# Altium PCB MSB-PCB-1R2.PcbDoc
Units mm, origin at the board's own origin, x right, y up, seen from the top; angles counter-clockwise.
Board outline 51 x 51 mm, 2 copper layers (Top Layer, Bottom Layer), stack 1.57 mm thick; 48 components, 55 nets, 221 pads, 21 vias.
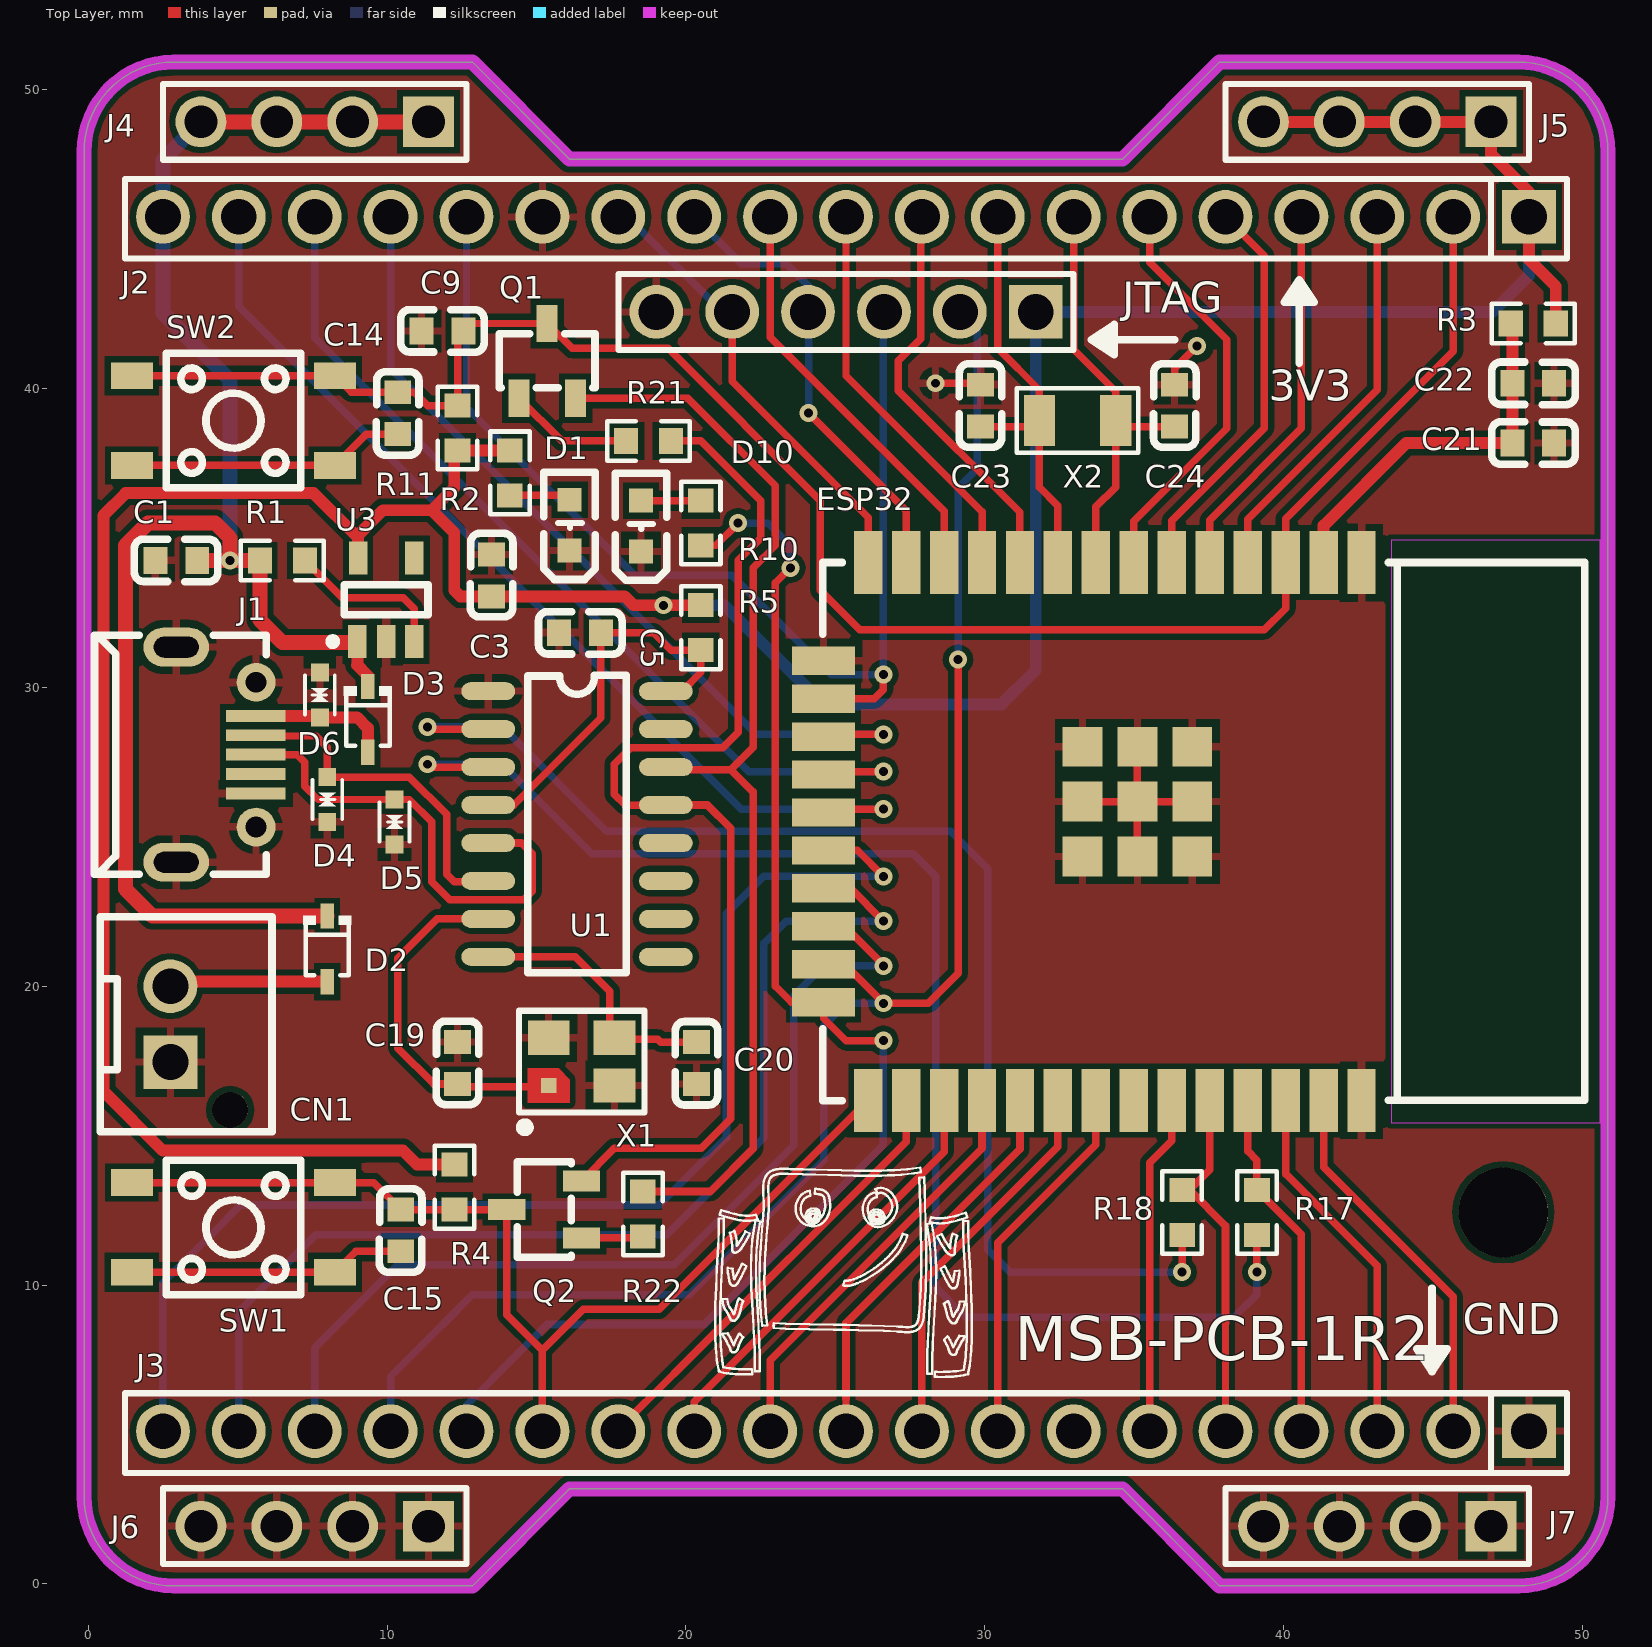
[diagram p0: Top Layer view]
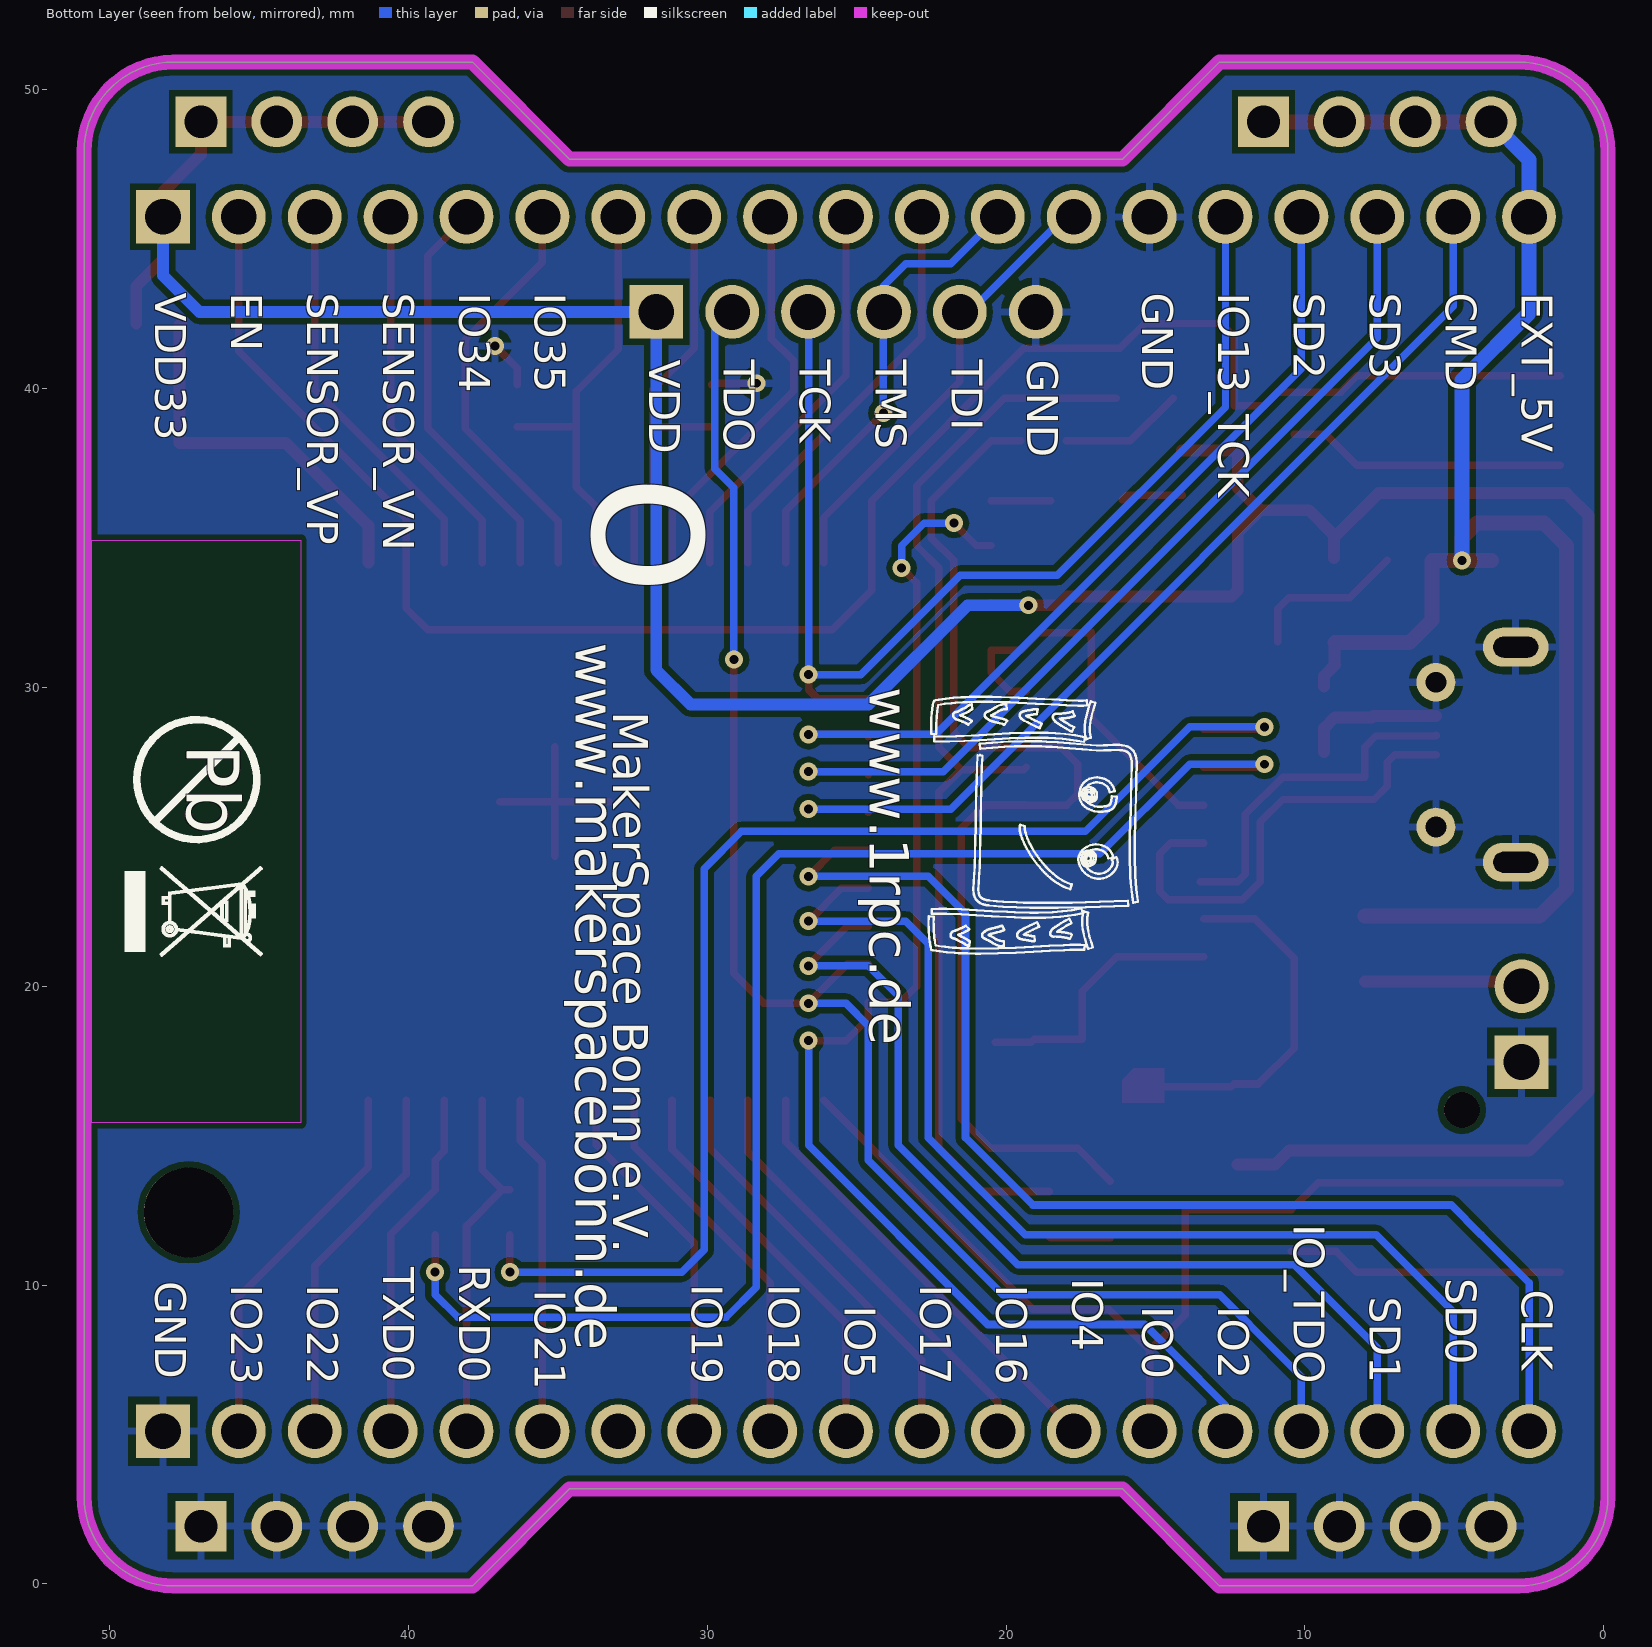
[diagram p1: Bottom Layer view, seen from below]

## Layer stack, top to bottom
Top Solder: solder mask 0.01, Solder Resist, Dk 3.5
Top Layer: signal copper 0.035
Dielectric 1: dielectric 1.5, FR-4, Dk 4.8
Bottom Layer: signal copper 0.035
Bottom Solder: solder mask 0.01, Solder Resist, Dk 3.5

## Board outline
-0.14,2.93 ccw(c2.86,2.93) 2.86,-0.07 12.86,-0.07 16.11,3.18 34.61,3.18 37.86,-0.07 47.86,-0.07 ccw(c47.86,2.93) 50.86,2.93 50.86,47.93 ccw(c47.86,47.93) 47.86,50.93 37.86,50.93 34.61,47.68 16.11,47.68 12.86,50.93 2.86,50.93 ccw(c2.86,47.93) -0.14,47.93

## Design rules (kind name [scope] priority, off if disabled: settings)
Clearance [All] p1: gap=0.2 ignorepadtopadclearanceinfootprint=FALSE
ComponentClearance [All] p1: gap=0.2 collisioncheckmode=3 verticalgap=0.2 showdistances=FALSE
HoleSize [All] p1: absolutevalues=TRUE maxlimit=3.5 minlimit=0.025 maxpercent=80.000 minpercent=20.000
MinimumSolderMaskSliver [All] p1: minsoldermaskwidth=0.05
PolygonConnect [All] p1: connectstyle=Relief reliefconductorwidth=0.254 reliefentries=4 polygonreliefangle="90 Angle" airgapwidth=0.254
RoomDefinition MSB-PCB-1R2 [InComponentClass('MSB-PCB-1R2')] p1: confinementstyle=ConfineIn formatcopy=TRUE lockcomponents=FALSE outline -0.14,-0.07 50.86,-0.07 50.86,50.93 -0.14,50.93
RoutingVias [All] p1: holewidth=0.3 width=0.6 viastyle="Through Hole" minholewidth=0.3 minwidth=0.6 maxholewidth=0.7 maxwidth=1
SilkToSilkClearance [All] p1 off: silktosilkclearance=0.1
SilkToSolderMaskClearance [IsPad] p1: minsilkscreentomaskgap=0.1 clearancetoexposedcopper=TRUE
SolderMaskExpansion [All] p1: expansion=0.102
Width [All] p1: maxlimit=0.6 minlimit=0.2 preferedwidth=0.25
25 further rules are at their usual default settings.

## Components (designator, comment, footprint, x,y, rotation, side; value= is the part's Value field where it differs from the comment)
C1 "22uF" C0603 2.95,34.25 r0 top
C3 "22uF" C0603 13.5,33.75 r270 top
C5 "100nF" C0603 16.46,31.83 r180 top
C9 "100nF" C0603 11.86,41.93 r0 top
C14 "100nF" C0603 10.36,39.18 r90 top
C15 "100nF" C0603 10.46,11.83 r90 top
C19 "20pF" C0603 12.36,17.43 r270 top
C20 "20pF" C0603 20.36,17.43 r90 top
C21 "22uF" C0603 48.36,38.18 r180 top
C22 "100nF" C0603 48.36,40.18 r180 top
C23 "12pF" C0603 29.86,39.43 r270 top
C24 "12pF" C0603 36.36,39.43 r270 top
CN1 "B2B-XH-AM (LF)(SN)" CONN-TH_B2B-XH-AM-LF-SN 2.75,18.73 r270 top
D1 "19-217/GHC-YR1S2/3T" LED0603-R-RD 16.11,35.43 r90 top
D2 "BAT760-7" SOD-323_L1.8-W1.3-LS2.5-RD 8,21.25 r270 top
D3 "BAT760-7" SOD-323_L1.8-W1.3-LS2.5-RD 9.36,28.93 r270 top
D4 "LESD5D5.0CT1G" SOD-523_L1.2-W0.8-LS1.6-BI 8,26.25 r90 top
D5 "LESD5D5.0CT1G" SOD-523_L1.2-W0.8-LS1.6-BI 10.25,25.5 r90 top
D6 "LESD5D5.0CT1G" SOD-523_L1.2-W0.8-LS1.6-BI 7.75,29.75 r270 top
D10 "19-217/BHC-ZL1M2RY/3T" LED0603-R-RD 18.5,35.399 r90 top
ESP32 "ESP32-WROOM-32E(4MB)" WIFI-SMD_ESP32-WROOM-32E 33.61,25.18 r180 top
J1 "MICROXNJ" MICRO-USB-SMD_MICROXNJ 4.283,27.75 r270 top
J2 "12251120CNG0S115005" HDR-TH_19P-P2.54-V 24.09,45.75 r180 top
J3 "12251120CNG0S115005" HDR-TH_19P-P2.54-V 24.09,5.11 r180 top
J4 "MTP125-1104S1" HDR-TH_4P-P2.54-V 7.58,48.93 r180 top
J5 "MTP125-1104S1" HDR-TH_4P-P2.54-V 43.14,48.93 r180 top
J6 "MTP125-1104S1" HDR-TH_4P-P2.54-V 7.58,1.93 r180 top
J7 "MTP125-1104S1" HDR-TH_4P-P2.54-V 43.14,1.93 r180 top
JTAG "MTP125-1106S1" HDR-TH_6P-P2.54-V 25.36,42.57 r180 top
Q1 "S8050_C2146" SOT-23-3_L3.0-W1.7-P0.95-LS2.9-BR 15.36,40.93 r270 top
Q2 "S8050_C2146" SOT-23-3_L3.0-W1.7-P0.95-LS2.9-BR 15.26,12.53 r0 top
R1 "1.8K" R0603 6.497,34.25 r0 top
R2 "560" R0603 14.11,37.18 r90 top
R3 "0" R0603 48.36,42.18 r180 top
R4 "10K" R0603 12.26,13.277 r90 top
R5 "0" R0603 20.5,32 r90 top
R10 "560" R0603 20.5,35.503 r270 top
R11 "10K" R0603 12.36,38.68 r270 top
R17 "270" R0603 39.11,12.43 r270 top
R18 "270" R0603 36.61,12.43 r270 top
R21 "10K" R0603 18.75,38.25 r180 top
R22 "10K" R0603 18.56,12.377 r270 top
SW1 "GT-TC074A-H038-L1" SW-SMD_4P-L4.5-W4.5-P3.00-LS7.0 4.86,11.93 r180 top
SW2 "GT-TC074A-H038-L1" SW-SMD_4P-L4.5-W4.5-P3.00-LS7.0 4.86,38.93 r180 top
U1 "CH340G" SOIC-16_L9.9-W3.9-P1.27-LS6.0-TL 16.36,25.43 r270 top
U3 "AP2112K-3.3TRG1" SOT-25-5_L3.0-W1.8-P0.95-LS3.0-BR 9.96,32.93 r270 top
X1 "12MHz" OSC-SMD_4P-L3.2-W2.5-BL 16.51,17.48 r0 top
X2 "32.768KHz" OSC-SMD_L3.2-W1.5 33.11,38.93 r0 top

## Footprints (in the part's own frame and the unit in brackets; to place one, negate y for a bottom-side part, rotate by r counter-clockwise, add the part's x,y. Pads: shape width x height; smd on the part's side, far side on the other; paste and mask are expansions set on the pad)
C0603 [mm]
  rect 0.8x0.9 smd: 1(-0.7,0) 2(0.7,0)
  silkscreen extent -1.41,-0.71 1.39,0.72
CONN-TH_B2B-XH-AM-LF-SN [mm]
  rect 1.8x1.8 hole 1.2: 1(1.27,0)
  round 1.8 hole 1.2: 2(-1.27,0)
  round 1.2 hole 1.2 unplated: ""(2.87,2)
  silkscreen extent -3.6,-2.35 3.6,3.4
HDR-TH_4P-P2.54-V [mm]
  rect 1.7x1.7 hole 1.1: 1(-3.81,0)
  round 1.7 hole 1.1: 2(-1.27,0) 3(1.27,0) 4(3.81,0)
  silkscreen extent -5.08,-1.27 5.08,1.27
HDR-TH_6P-P2.54-V [mm]
  rect 1.8x1.8 hole 1.2: 1(-6.35,0)
  round 1.8 hole 1.2: 2(-3.81,0) 3(-1.27,0) 4(1.27,0) 5(3.81,0) 6(6.35,0)
  silkscreen extent -7.62,-1.27 7.62,1.27
HDR-TH_19P-P2.54-V [mm]
  rect 1.8x1.8 hole 1.2: 1(-24.13,0)
  round 1.8 hole 1.2: 2(-21.59,0) 3(-19.05,0) 4(-16.51,0) 5(-13.97,0) 6(-11.43,0) 7(-8.89,0) 8(-6.35,0) 9(-3.81,0) 10(-1.27,0) 11(1.27,0) 12(3.81,0) 13(6.35,0) 14(8.89,0) 15(11.43,0) 16(13.97,0) 17(16.51,0) 18(19.05,0) 19(21.59,0)
  silkscreen extent -25.4,-1.27 22.86,1.4
LED0603-R-RD [mm]
  rect 0.8x0.8 smd: 1(0.851,0) 2(-0.851,0)
  silkscreen extent -1.82,-0.86 1.77,0.86
MICRO-USB-SMD_MICROXNJ [mm]
  rect 0.4x2 smd mask+0: 1(-1.3,1.327) 2(-0.65,1.327) 3(0,1.327) 4(0.65,1.327) 5(1.3,1.327)
  round 1.3 hole 0.7: 6(2.425,1.335) 9(-2.425,1.335)
  oval 1.3x2.2 hole 0.7 slot 1.5 at 90 deg: 7(3.6,-1.335) 8(-3.6,-1.335)
  silkscreen extent -4,-4.07 4,1.68
OSC-SMD_4P-L3.2-W2.5-BL [mm]
  rect 0.508x0.508 smd: 1(-1.1,-0.8)
  rect 1.4x1.15 smd: 2(1.1,-0.8) 3(1.1,0.8) 4(-1.1,0.8)
  Top Layer region: -1.8,-0.225 -0.762,-0.225 -0.4,-0.604 -0.4,-1.375 -1.8,-1.375
  silkscreen extent -2.1,-2.35 2.1,1.7
OSC-SMD_L3.2-W1.5 [mm]
  rect 1.05x1.7 smd: 1(-1.275,0) 2(1.275,0)
  silkscreen extent -2.03,-1.08 2.03,1.08
R0603 [mm]
  rect 0.806x0.864 smd: 1(-0.753,0) 2(0.753,0)
  silkscreen extent -1.39,-0.66 1.39,0.66
SOD-323_L1.8-W1.3-LS2.5-RD [mm]
  rect 0.845x0.455 smd: 1(-1.098,0) 2(1.098,0)
  silkscreen extent -1.1,-0.8 0.88,0.8
SOD-523_L1.2-W0.8-LS1.6-BI [mm]
  rect 0.6x0.6 smd: 1(-0.75,0) 2(0.75,0)
  silkscreen extent -0.65,-0.5 0.65,0.5
SOIC-16_L9.9-W3.9-P1.27-LS6.0-TL [mm]
  oval 0.6x1.8 smd: 1(-4.445,-2.972) 2(-3.175,-2.972) 3(-1.905,-2.972) 4(-0.635,-2.972) 5(0.635,-2.972) 6(1.905,-2.972) 7(3.175,-2.972) 8(4.445,-2.972) 9(4.445,2.972) 10(3.175,2.972) 11(1.905,2.972) 12(0.635,2.972) 13(-0.635,2.972) 14(-1.905,2.972) 15(-3.175,2.972) 16(-4.445,2.972)
  silkscreen extent -4.98,-1.65 4.98,1.65
SOT-23-3_L3.0-W1.7-P0.95-LS2.9-BR [mm]
  rect 1.25x0.7 smd: 1(1.25,-0.95) 2(1.25,0.95) 3(-1.25,0)
  silkscreen extent -0.9,-1.6 0.9,1.6
SOT-25-5_L3.0-W1.8-P0.95-LS3.0-BR [mil]
  rect 43.5x24.5 smd: 1(55,-37.5) 2(55,0.5) 3(55,37.5) 4(-55,37.5) 5(-55,-36.5)
  silkscreen extent -20,-75 60,56
SW-SMD_4P-L4.5-W4.5-P3.00-LS7.0 [mm]
  rect 1.4x0.9 smd: 1(-3.4,1.5) 2(3.4,1.5) 3(-3.4,-1.5) 4(3.4,-1.5)
  silkscreen extent -2.25,-2.25 2.25,2.25
WIFI-SMD_ESP32-WROOM-32E [mm]
  rect 0.95x2.1 smd: 1(-9.002,-9) 2(-7.732,-9) 3(-6.462,-9) 4(-5.192,-9) 5(-3.922,-9) 6(-2.652,-9) 7(-1.382,-9) 8(-0.112,-9) 9(1.158,-9) 10(2.428,-9) 11(3.698,-9) 12(4.968,-9) 13(6.238,-9) 14(7.508,-9) 25(7.507,9) 26(6.237,9) 27(4.967,9) 28(3.697,9) 29(2.427,9) 30(1.157,9) 31(-0.113,9) 32(-1.383,9) 33(-2.653,9) 34(-3.923,9) 35(-5.193,9) 36(-6.463,9) 37(-7.733,9) 38(-9.003,9)
  rect 2.1x0.95 smd: 15(9.002,-5.715) 16(9.002,-4.445) 17(9.002,-3.175) 18(9.002,-1.905) 19(9.002,-0.635) 20(9.002,0.635) 21(9.002,1.905) 22(9.002,3.175) 23(9.002,4.445) 24(9.002,5.715)
  rect 1.33x1.33 smd: 39(-3.337,-2.835) 39(-3.337,-1) 39(-3.337,0.835) 39(-1.502,0.835) 39(-1.502,-1) 39(-1.502,-2.835) 39(0.333,0.835) 39(0.333,-1) 39(0.333,-2.835)
  silkscreen extent -16.48,-9 9.02,9.02

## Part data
C1 C3 C21: BOM_JLCPCB Part Class="Extended Part", BOM_Manufacturer="Murata Electronics", BOM_Manufacturer Part=GRM188R61A226ME15L
C5 C9 C14 C15 C22: BOM_JLCPCB SMD=Yes, BOM_Manufacturer=YAGEO, BOM_Manufacturer Part=CC0603KRX7R9BB104
C19 C20: BOM_Manufacturer=CCTC, BOM_Manufacturer Part=TCC0603COG200J500CT
C23 C24: BOM_Manufacturer=CCTC, BOM_Manufacturer Part=TCC0603COG120J500CT
CN1: BOM_JLCPCB Part Class="Extended Part", BOM_Manufacturer="JST Sales America", BOM_Manufacturer Part=-
D1 D10: BOM_JLCPCB Part Class="Basic Part", BOM_Manufacturer=EVERLIGHT
D2 D3: BOM_JLCPCB Part Class="Extended Part", BOM_Manufacturer=DIODES
D4 D5 D6: BOM_JLCPCB Part Class="Extended Part", BOM_Manufacturer="Leshan Radio"
ESP32: BOM_LCSC Assembly=Yes, BOM_Manufacturer="Espressif Systems"
J1: BOM_Manufacturer="SHOU HAN", BOM_Manufacturer Part=MicroXNJ
J2 J3: BOM_JLCPCB Part Class="Extended Part", BOM_Manufacturer=JILN
J4 J5 J6 J7 JTAG: BOM_JLCPCB Part Class="Extended Part", BOM_Manufacturer=MINTRON
Q1 Q2: BOM_JLCPCB SMD=Yes, BOM_Manufacturer=CJ, BOM_Manufacturer Part=S8050
R1: BOM_JLCPCB Part Class="Extended Part", BOM_Manufacturer=UniOhm, BOM_Manufacturer Part=0603WAJ0182T5E
R2 R10: BOM_JLCPCB Part Class="Basic Part", BOM_Manufacturer=UniOhm, BOM_Manufacturer Part=0603WAF5600T5E
R3 R5: BOM_JLCPCB SMD=Yes, BOM_Manufacturer=UniOhm, BOM_Manufacturer Part=0603WAF0000T5E
R4 R11 R21 R22: BOM_JLCPCB Part Class="Extended Part", BOM_Manufacturer=UniOhm, BOM_Manufacturer Part=0603WAJ0103T5E
R17 R18: BOM_JLCPCB Part Class="Extended Part", BOM_Manufacturer=UniOhm, BOM_Manufacturer Part=0603WAJ0271T5E
SW1 SW2: BOM_JLCPCB Part Class="Extended Part", BOM_Manufacturer=G-Switch
U1: BOM_JLCPCB SMD=Yes, BOM_Manufacturer=WCH
U3: BOM_JLCPCB SMD=Yes, BOM_Manufacturer=DIODES
X1: BOM_JLCPCB SMD=Yes, BOM_Manufacturer=YXC, BOM_Manufacturer Part=X322512MSB4SI
X2: BOM_JLCPCB Part Class="Extended Part", BOM_Manufacturer=TKD, BOM_Manufacturer Part=SF32K32768D31T-12.5

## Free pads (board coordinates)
  round 3 hole 3 unplated mask+1: 0(47.36,12.43)

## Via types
v1: diameter 0.6, hole 0.3, Top Layer to Bottom Layer, 21 vias

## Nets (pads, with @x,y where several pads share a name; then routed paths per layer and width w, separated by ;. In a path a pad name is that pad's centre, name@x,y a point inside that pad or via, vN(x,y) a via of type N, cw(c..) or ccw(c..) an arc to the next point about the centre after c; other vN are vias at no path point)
CLK: ESP32.20 J3.19 | length 41.5
  Top Layer w0.25: ESP32.20 25.745,24.545 v1(26.61,23.68)
  Bottom Layer w0.25: J3.19 2.5,10.07 4.11,11.68
  Bottom Layer w0.254: 4.11,11.68 5.11,12.68 19.11,12.68 21.36,14.93 21.36,22.43 22.61,23.68 v1(26.61,23.68)
CMD: ESP32.19 J2.18 | length 33.6
  Top Layer w0.25: ESP32.19 24.723,25.93 v1(26.61,25.93)
  Bottom Layer w0.25: J2.18 5.04,42.75 21.86,25.93 v1(26.61,25.93)
DTR: Q2.2 R21.1 U1.13 | length 37.4
  Top Layer w0.25: U1.13 17.975,26.065 17.61,26.43 17.61,27.43 18.16,27.98 21.23,27.98 21.75,28.5 21.75,34.25 22.5,35 22.5,36.25 20.5,38.25 R21.1
  Top Layer w0.254: Q2.2 17.61,14.58 20.51,14.58 21.5,15.57 21.5,25.29 20.725,26.065 U1.13
EN: C9.2 C14.2 ESP32.3 J2.2 Q1.3 R11.1 SW2.3 SW2.4 | length 63.2
  Top Layer w0.25: SW2.4 SW2.3 8.81,39.88 10.91,39.88 11.357,39.433 R11.1 12.36,41.73 C9.2 12.81,42.18 Q1.3 16.195,41.345 19.405,41.345 24.5,36.25 24.5,33.25 25.82,31.93 39.36,31.93 40.072,32.642 ESP32.3 40.072,35.642 45.68,41.25 J2.2
EXT_5V: C1.2 D2.1 D3.1 J2.19 J4.1 J4.2 J4.3 J4.4 R1.1 U3.1 | length 56.3
  Top Layer w0.4: 9,30.75 9.36,30.39 D3.1 ; 9.007,30.783 U3.1
  Top Layer w0.5: C1.2@3.75,34.25 v1(4.75,34.25) ; J4.4 J4.3 J4.2 J4.1 ; D2.1 2.152,22.348 1.25,23.25 1.25,34.75 2,35.5 4.25,35.5 4.75,35 v1(4.75,34.25) ; U3.1@9,31.5 6.5,31.5 5.744,32.256 R1.1 v1(4.75,34.25)
  Bottom Layer w0.5: J4.4 2.5,47.66 J2.19 2.5,42.53 4.75,40.28 v1(4.75,34.25)
GND: C1.1 C3.1 C5.2 C9.1 C19.1 C20.1 C21.1 C22.1 C23.1 C24.1 CN1.1 D1.2 D4.1 D5.1 D6.1 D10.2 ESP32.1 ESP32.15 ESP32.38 ESP32.39 J1.5 J1.6 J1.7 J1.8 J1.9 J2.14 J3.1 J6.1 J6.2 J6.3 J6.4 J7.1 J7.2 J7.3 J7.4 JTAG.6 U1.1 U3.2 X1.2 X1.4 | length 11.1
  Top Layer w0.25: J2.14 J2.14@15.2,46.39 ; v1(28.36,40.18) 29.81,40.18 C23.1 ; ESP32.39@33.277,26.18 ESP32.39@35.112,26.18 ; ESP32.39@35.112,24.345 ESP32.39@35.112,26.18 ; ESP32.39@35.112,28.015 ESP32.39@35.112,26.18 ; C24.1 36.36,40.68 v1(37.11,41.43) ; ESP32.39@36.947,26.18 ESP32.39@35.112,26.18
IO0: C15.2 ESP32.25 J3.14 Q2.3 R4.1 SW1.3 SW1.4 | length 35.2
  Top Layer w0.25: SW1.4 9.56,13.43 10.466,12.524 14.004,12.524 Q2.3 14.01,9.007 15.2,7.817 16.57,9.187 19.11,9.187 ESP32.25 ; J3.14 15.2,7.77
IO2: ESP32.24 J3.15 R10.2 | length 45.2
  Top Layer w0.25: R10.2 21,34.75 v1(21.75,35.5) ; v1(23.5,34) 23,33.5 23,20 23.535,19.465 ESP32.24 24.608,18.932 25.36,18.18 v1(26.61,18.18)
  Bottom Layer w0.25: J3.15 12.66,5.98 14.36,7.68 ; v1(21.75,35.5) 22.75,35.5 23.5,34.75 v1(23.5,34)
  Bottom Layer w0.254: 14.36,7.68 15.36,8.68 20.61,8.68 26.61,14.68 v1(26.61,18.18)
IO4: ESP32.26 J3.13 | length 15.1
  Top Layer w0.25: J3.13 17.74,5.17 19.61,7.04
  Top Layer w0.254: 19.61,7.04 27.373,14.803 ESP32.26
IO5: ESP32.29 J3.10 | length 13.5
  Top Layer w0.25: J3.10 25.36,6.18
  Top Layer w0.254: 25.36,6.18 25.36,8.73 31.183,14.553 ESP32.29
IO12_TDI: ESP32.14 J2.13 JTAG.5 | length 15.4
  Top Layer w0.25: JTAG.5 21.55,40.24 26.102,35.688 ESP32.14
  Bottom Layer w0.25: J2.13 18.04,45.75 21.22,42.57 JTAG.5
IO13_TCK: ESP32.16 J2.15 JTAG.3 | length 38.8
  Top Layer w0.25: ESP32.16 26.305,29.625 26.61,29.93 v1(26.61,30.43)
  Bottom Layer w0.25: J2.15 12.66,39.38 18.29,33.75 21.54,33.75 24.86,30.43 v1(26.61,30.43) 26.61,42.55 JTAG.3
IO14_TMS: ESP32.13 J2.12 JTAG.4 | length 15.5
  Top Layer w0.25: J2.12 J2.12@20.325,45.705 ; v1(24.11,39.18) 27.372,35.918 ESP32.13
  Bottom Layer w0.25: J2.12 21.85,44.18 23.36,44.18 24.09,43.45 JTAG.4 24.11,42.55 v1(24.11,39.18)
IO15_TDO: ESP32.23 J3.16 JTAG.2 | length 54.2
  Top Layer w0.25: ESP32.23 25.322,20.735 26.61,19.447 v1(26.61,19.43) 28.11,19.43 29.11,20.43 v1(29.11,30.93)
  Bottom Layer w0.25: J3.16 10.12,6.94 11.86,8.68 ; v1(29.11,30.93) 29.11,36.68 29.75,37.32 29.75,41.99 JTAG.2
  Bottom Layer w0.254: 11.86,8.68 12.86,9.68 20.11,9.68 24.61,14.18 24.61,18.68 25.36,19.43 v1(26.61,19.43)
IO16: ESP32.27 J3.12 | length 14.5
  Top Layer w0.25: J3.12 20.28,6.1 21.55,7.37
  Top Layer w0.254: 21.55,7.37 28.643,14.463 ESP32.27
IO17: ESP32.28 J3.11 | length 14
  Top Layer w0.25: J3.11 22.82,6.14
  Top Layer w0.254: 22.82,6.14 22.82,7.49 29.913,14.583 ESP32.28
IO18: ESP32.30 J3.9 | length 13
  Top Layer w0.25: J3.9 27.9,10.07
  Top Layer w0.254: 27.9,10.07 32.453,14.623 ESP32.30
IO19: ESP32.31 J3.8 | length 12.4
  Top Layer w0.25: J3.8 30.44,6.26
  Top Layer w0.254: 30.44,6.26 30.44,11.41 33.723,14.693 ESP32.31
IO21: ESP32.33 J3.6 | length 11.4
  Top Layer w0.25: J3.6 35.52,8.77
  Top Layer w0.254: 35.52,8.77 35.52,14.09 36.263,14.833 ESP32.33
IO22: ESP32.36 J3.3 | length 12.3
  Top Layer w0.25: 42.61,11.18 43.14,10.65 J3.3
  Top Layer w0.254: ESP32.36 40.073,13.717 42.61,11.18
IO23: ESP32.37 J3.2 | length 12.9
  Top Layer w0.25: 43.86,11.43 45.68,9.61 J3.2
  Top Layer w0.254: ESP32.37 41.343,13.947 43.86,11.43
IO25: ESP32.10 J2.9 | length 13.6
  Top Layer w0.25: J2.9 27.855,45.705 27.855,41.675 27.11,40.93 27.11,39.93 31.182,35.858 ESP32.10
IO26: ESP32.11 J2.10 | length 13.5
  Top Layer w0.25: J2.10 25.36,40.43 29.912,35.878 ESP32.11
IO27: ESP32.12 J2.11 | length 14
  Top Layer w0.25: J2.11 22.82,41.72 28.642,35.898 ESP32.12
IO32: C24.2 ESP32.8 J2.7 X2.2 | length 14.4
  Top Layer w0.25: J2.7 32.98,41.31 34.385,39.905 X2.2 X2.2@34.385,38.68 ; ESP32.8 33.722,36.042 34.385,36.705 X2.2@34.385,38.68 ; C24.2 34.435,38.73 X2.2@34.385,38.68
IO33: C23.2 ESP32.9 J2.8 X2.1 | length 14.5
  Top Layer w0.25: C23.2 31.635,38.73 X2.1 ; J2.8 30.44,41.35 31.835,39.955 X2.1 ; ESP32.9 32.452,36.088 31.835,36.705 X2.1
IO34: ESP32.6 J2.5 | length 13.4
  Top Layer w0.25: ESP32.6 36.262,35.582 39.36,38.68 39.36,44.45 J2.5
IO35: ESP32.7 J2.6 | length 13.9
  Top Layer w0.25: ESP32.7 34.992,35.562 38.11,38.68 38.11,41.64 35.52,44.23 J2.6
NetC14_1: C14.1 SW2.1 SW2.2 | length 9.3
  Top Layer w0.25: SW2.2 SW2.1 9.31,38.48 C14.1
NetC15_1: C15.1 SW1.1 SW1.2 | length 9.3
  Top Layer w0.25: SW1.2 SW1.1 8.96,11.13 C15.1
NetC19_2: C19.2 U1.7 X1.1 | length 12
  Top Layer w0.25: C19.2 12.46,16.63 X1.1@15.26,16.63
  Top Layer w0.254: C19.2 11.56,16.73 10.36,17.93 10.36,20.93 11.685,22.255 U1.7
NetC20_2: C20.2 U1.8 X1.3 | length 9.1
  Top Layer w0.254: U1.8 16.305,20.985 17.46,19.83 17.46,18.23 19.06,18.23 19.16,18.13 C20.2
NetCN1_2: CN1.2 D2.2 | length 5.3
  Top Layer w0.4: CN1.2 2.902,20.152 D2.2
NetD1_1: D1.1 R2.1 | length 2.1
  Top Layer w0.25: R2.1 15.964,36.427 D1.1
NetD10_1: D10.1 R10.1 | length 2
  Top Layer w0.25: D10.1 R10.1@20.494,36.25
NetQ1_1: Q1.1 R21.2 | length 4.2
  Top Layer w0.25: Q1.1 15.84,38.25 R21.2
NetQ2_1: Q2.1 R22.2 | length 2.1
  Top Layer w0.25: Q2.1 18.516,11.58 R22.2
NetR1_2: R1.2 U3.3 | length 5.4
  Top Layer w0.25: R1.2 8.5,33 10.54,33 10.912,32.628 U3.3
RTS: Q1.2 R22.1 U1.14 | length 37.5
  Top Layer w0.25: Q1.2 20.07,39.68 23,36.75 23,34.75 22.25,34 22.25,28 21.5,27.25
  Top Layer w0.254: R22.1 20.81,13.13 22.25,14.57 22.25,26.5 21.5,27.25 19.417,27.25 U1.14
RXD: R17.2 U1.3 | length 47.8
  Top Layer w0.25: v1(11.36,27.43) 11.455,27.335 U1.3 ; v1(39.11,10.43) R17.2
  Bottom Layer w0.25: v1(11.36,27.43) 13.86,27.43 16.86,24.43 27.61,24.43 28.36,23.68 28.36,9.93 29.36,8.93 38.36,8.93 39.11,9.68 v1(39.11,10.43)
RXD0: ESP32.34 J3.5 R18.1 | length 12.1
  Top Layer w0.25: J3.5 38.06,8.73
  Top Layer w0.254: R18.1 R18.1@36.857,13.183 ; ESP32.34 37.533,13.853 36.863,13.183 R18.1@36.857,13.183 ; 38.06,8.73 38.06,11.98 R18.1@36.857,13.183
SD0: ESP32.21 J3.18 | length 37.2
  Top Layer w0.25: ESP32.21 25.515,23.275 v1(26.61,22.18)
  Bottom Layer w0.25: J3.18 5.04,9.11 6.36,10.43
  Bottom Layer w0.254: 6.36,10.43 7.61,11.68 19.36,11.68 22.61,14.93 22.61,21.43 23.36,22.18 v1(26.61,22.18)
SD1: ESP32.22 J3.17 | length 32.6
  Top Layer w0.25: ESP32.22 25.322,22.005 26.61,20.717 v1(26.61,20.68)
  Bottom Layer w0.25: J3.17 7.58,7.9 9.605,9.925
  Bottom Layer w0.254: 9.605,9.925 10.36,10.68 19.61,10.68 23.61,14.68 23.61,19.68 24.61,20.68 v1(26.61,20.68)
SD2: ESP32.17 J2.16 | length 28.7
  Top Layer w0.25: ESP32.17 24.683,28.43 v1(26.61,28.43)
  Bottom Layer w0.25: J2.16 10.12,40.67 22.36,28.43 v1(26.61,28.43)
SD3: ESP32.18 J2.17 | length 31.1
  Top Layer w0.25: ESP32.18 24.703,27.18 v1(26.61,27.18)
  Bottom Layer w0.25: J2.17 7.58,41.71 22.11,27.18 v1(26.61,27.18)
SENSOR_VN: ESP32.5 J2.4 | length 12.8
  Top Layer w0.25: ESP32.5 37.532,35.602 40.6,38.67 J2.4
SENSOR_VP: ESP32.4 J2.3 | length 13.4
  Top Layer w0.25: ESP32.4 38.802,35.622 43.14,39.96 J2.3
TXD: R18.2 U1.2 | length 43.6
  Top Layer w0.25: v1(11.36,28.68) 11.435,28.605 U1.2 ; v1(36.61,10.43) R18.2
  Bottom Layer w0.25: v1(11.36,28.68) 13.86,28.68 17.36,25.18 28.86,25.18 30.11,23.93 30.11,11.18 30.86,10.43 v1(36.61,10.43)
TXD0: ESP32.35 J3.4 R17.1 | length 11.8
  Top Layer w0.25: 40.49,11.803 40.6,11.693 J3.4
  Top Layer w0.254: ESP32.35 38.803,14.487 39.11,14.18 R17.1 40.49,11.803
USB_DN: D4.2 J1.2 U1.6 | length 11.7
  Top Layer w0.25: J1.2 5.61,28.375 7.625,28.375 8,28 D4.2 10.75,27 12,25.75 12,23.75 12.25,23.5 U1.6@13.5,23.5
USB_DP: D5.2 J1.3 U1.5 | length 15.9
  Top Layer w0.25: J1.3 7,27.75 7.25,27.5 7.25,26.69 7.69,26.25 D5.2 10.75,26.25 11.5,25.5 11.5,23.5 12.102,22.898 12.5,22.898
  Top Layer w0.254: 12.5,22.898 14.578,22.898 14.86,23.18 14.86,24.43 14.495,24.795 U1.5
VBUS: D3.2 D6.2 J1.1 | length 4.7
  Top Layer w0.4: J1.1 D6.2@7.7,29.05 ; D6.2 8.75,29 9,29 9.36,28.64 D3.2
VDD33: C3.2 J2.1 J5.1 J5.2 J5.3 J5.4 JTAG.1 R2.2 R3.1 R4.2 R5.2 R11.2 U3.5 | length 121.2
  Top Layer w0.4: U3.5 9.033,35.007 ; R4.2 11.01,14.03 10.54,14.5 2.5,14.5 0.51,16.49 0.51,35.76 1.25,36.5 7.54,36.5 9.033,35.007 ; R2.2 14.104,37.927 12.25,37.927 12.25,36.68 11.5,35.93 ; R5.2 20.497,32.75 v1(19.25,32.75) 18.25,32.75 17.95,33.05 C3.2 12.45,33.05 12.25,33.25 12.25,35.18 11.5,35.93 ; J5.4 J5.3 J5.2 J5.1 46.95,47.84 48.22,46.57 J2.1 48.22,44.32 49.113,43.427 R3.1 ; 9.033,35.007 9.033,35.103 9.86,35.93 11.5,35.93
  Bottom Layer w0.4: v1(19.25,32.75) 21.29,32.75 24.61,29.43 30.56,29.43 31.71,30.58 JTAG.1 47,42.57 48.22,43.79 J2.1
VDD_ESP: C21.2 C22.2 ESP32.2 R3.2 | length 12.7
  Top Layer w0.4: ESP32.2 41.342,35.412 44.11,38.18 C21.2 47.66,42.127 R3.2
VDD_U1: C5.1 R5.1 U1.4 U1.16 | length 13.6
  Top Layer w0.25: U1.4 14.245,26.065 17.16,28.98 C5.1@17.16,31.84 ; C5.1 18.92,31.83 19.503,31.247 R5.1 20.5,30.5 19.875,29.875 U1.16
pads on no net: CN1. ESP32.32 J1.4 J3.7 U1.9 U1.10 U1.11 U1.12 U1.15 U3.4

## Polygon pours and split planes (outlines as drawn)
GND on Bottom Layer "Bottom Layer-GND" (solid, remove dead copper, pour order 0): -0.14,-0.07 -0.14,50.93 51.11,50.93 50.86,50.68 50.86,-0.07
GND on Top Layer "Top Layer-GND" (solid, remove dead copper, pour order 2): -0.14,-0.07 -0.14,50.93 51.11,50.93 50.86,50.68 50.86,-0.07

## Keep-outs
Keep-Out Layer:
  region: 43.61,34.93 43.61,15.43 50.61,15.43 50.61,34.93
  lines w0.5: -0.14,2.93 ccw(c2.86,2.93) 2.86,-0.07 12.86,-0.07 16.11,3.18 34.61,3.18 37.86,-0.07 47.86,-0.07 ccw(c47.86,2.93) 50.86,2.93 50.86,47.93 ccw(c47.86,47.93) 47.86,50.93 37.86,50.93 34.61,47.68 16.11,47.68 12.86,50.93 2.86,50.93 ccw(c2.86,47.93) -0.14,47.93 -0.14,2.93

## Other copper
Top Layer:
  text "1. Logo anklicken" at -43.54,-12.398 h2
  text "2. Rechte Maustaste Unions->Resize Union" at -43.539,-13.922 h2
  text "3. Logo erneut anklicken -> Union ist selektiert" at -43.54,-15.446 h2
  text "4. nun skalieren, wie gewohnt" at -43.54,-16.97 h2

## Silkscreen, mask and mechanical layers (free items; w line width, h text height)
Top Overlay:
  drawing of 1641 lines, arcs and shapes, not listed
  text "3V3" at 39.5,39.25 h1.78
  text "GND" at 46,8 h1.78
  text "MSB-PCB-1R2" at 31,7 h2.54
Bottom Overlay:
  drawing of 4921 lines, arcs and shapes, not listed
  text "EXT_5V" at 3.1,43.21 h1.78 r90
  text "CMD" at 5.64,43.21 h1.78 r90
  text "SD3" at 8.18,43.21 h1.78 r90
  text "SD2" at 10.72,43.21 h1.78 r90
  text "IO13_TCK" at 13.26,43.21 h1.78 r90
  text "GND" at 15.8,43.21 h1.78 r90
  text "IO35" at 36.12,43.21 h1.78 r90
  text "IO34" at 38.66,43.21 h1.78 r90
  text "SENSOR_VN" at 41.2,43.21 h1.78 r90
  text "SENSOR_VP" at 43.74,43.21 h1.78 r90
  text "EN" at 46.28,43.21 h1.78 r90
  text "VDD33" at 48.82,43.21 h1.78 r90
  text "GND" at 19.64,40.96 h1.78 r90
  text "TDI" at 22.18,40.96 h1.78 r90
  text "TMS" at 24.72,40.96 h1.78 r90
  text "TCK" at 27.26,40.96 h1.78 r90
  text "TDO" at 29.8,40.96 h1.78 r90
  text "VDD" at 32.3,40.96 h1.78 r90
  text "o" at 35.52,33.05 h9 r90
  text "www.makerspacebonn.de" at 34.84,31.5 h2.29 r90
  text "www.1rpc.de" at 25,30 h2.29 r90
  text "MakerSpace Bonn e.V." at 33.54,29.2 h2 r90
  text "Pb" at 48.001,28.107 h3.05 r90
  text "IO_TDO" at 10.72,12.027 h1.78 r90
  text "RXD0" at 38.66,10.681 h1.78 r90
  text "TXD0" at 41.2,10.604 h1.78 r90
  text "SD0" at 5.64,10.225 h1.78 r90
  text "IO4" at 18.14,10.225 h1.78 r90
  text "GND" at 48.82,10.13 h1.78 r90
  text "IO16" at 20.68,10.018 h1.78 r90
  text "IO17" at 23.22,10.018 h1.78 r90
  text "IO18" at 28.3,10.021 h1.78 r90
  text "IO19" at 30.87,10.021 h1.78 r90
  text "IO23" at 46.28,10.018 h1.78 r90
  text "IO22" at 43.74,10.011 h1.78 r90
  text "CLK" at 3.1,9.851 h1.78 r90
  text "IO21" at 36.12,9.838 h1.78 r90
  text "SD1" at 8.18,9.616 h1.78 r90
  text "IO5" at 25.76,9.308 h1.78 r90
  text "IO2" at 13.26,9.295 h1.78 r90
  text "IO0" at 15.8,9.298 h1.78 r90
Bottom Solder:
  text "2021 NEK" at 50.5,41.5 h1.78 r90
M1_Board Outline:
  the board outline again, w0.5
M2_Dimensions:
  lines w0.05: -0.14,-0.07 50.86,50.93 ; -0.14,25.43 50.86,25.43 ; -0.14,50.93 50.86,-0.07
M23_Template A4:
  lines w0.2: -11.413,-53.87 -11.413,-48.87 ; -11.413,129.13 -11.413,134.13 ; 59.587,-53.87 59.587,-48.87 ; 59.587,129.13 59.587,134.13 ; 103.76,-39.47 169.76,-39.47 ; 103.86,-30.46 202.576,-30.46 ; 129.037,-48.77 129.037,-39.57 ; 129.06,-46.352 202.576,-46.352 ; 129.06,-43.87 169.76,-43.87 ; 129.06,-41.37 169.76,-41.37 ; 130.587,-53.87 130.587,-48.87 ; 130.587,129.13 130.587,134.13 ; 169.837,-48.87 169.837,-30.47 ; 169.851,-42.041 202.413,-42.041 ; 169.86,-44.518 202.568,-44.518 ; 169.86,-32.274 202.522,-32.274 ; 169.951,-38.741 202.513,-38.741 ; 169.951,-36.941 202.513,-36.941 ; -77.413,-53.87 207.587,-53.87 207.587,134.13 -77.413,134.13 -77.413,-53.87 ; -72.413,-48.87 202.587,-48.87 202.587,129.13 -72.413,129.13 -72.413,-48.87
  lines w0.254: -77.413,-6.87 -72.413,-6.87 ; -77.413,40.13 -72.413,40.13 ; -77.413,87.13 -72.413,87.13 ; 103.787,-48.77 103.787,-30.47 ; 140.56,-48.77 140.587,-39.57 ; 155.76,-39.57 155.78,-46.27 ; 182.952,-44.57 182.965,-48.77 ; 189.852,-44.57 189.865,-48.77 ; 202.56,39.762 207.56,39.762 ; 202.587,-6.87 207.587,-6.87 ; 202.646,87.921 207.546,87.921
  text "1" at -43.663,130.88 h3
  text "2" at 24.337,130.88 h3
  text "3" at 94.837,130.88 h3
  text "4" at 171.587,130.88 h3
  text "A" at -75.413,109.88 h3
  text "A" at 204.587,108.91 h3
  text "B" at 204.546,64.621 h3
  text "B" at -75.413,63.38 h3
  text "C" at -75.413,16.13 h3
  text "C" at 204.546,15.921 h3
  text "File:" at 103.86,-29.27 h2.1
  text "'.DocumentName" at 107.96,-29.27 h2.1
  text "D" at -75.413,-31.12 h3
  text "PCB Nr." at 184.16,-31.77 h1.9
  text "D" at 204.587,-32.62 h3
  text "'.Prj_SchematicMainTitle'" at 119.752,-34.385 h4
  text "Assembly Nr." at 181.98,-38.394 h1.9
  text "Date" at 147.06,-40.77 h1.9
  text "Name" at 161.26,-40.77 h1.9
  text "Drawn by" at 130.36,-42.97 h2.1
  text "'.PRJ_Layouter'" at 156.11,-43.171 h2.1
  text "15.06.2021" at 144.582,-43.354 h2.1
  text "Variant:" at 171.158,-43.954 h2.1
  text "microUSB" at 176.61,-44.57 h2.1
  text "Approved" at 130.36,-45.47 h2.1
  text "'.Prj_ApproverDate'" at 141.377,-45.763 h2.1
  text "'.Prj_ApproverName'" at 155.451,-45.763 h2.1
  text "Status" at 174.456,-45.956 h1.9
  text "Format" at 184.256,-45.956 h1.9
  text "o" at 112.86,-46.57 h11
  text "'.Prj_CompanySiteName'" at 107.721,-47.996 h2.1
  text "'.Prj_AssemblyVariantStatus'" at 173.11,-48.07 h2.1
  text "Cluster" at 130.36,-48.17 h2.1
  text "'.Prj_CompanyClusterName'" at 145.959,-48.263 h2.1
  text "A4" at 185.466,-48.364 h2.1
  text "1" at -45.163,-52.12 h3
  text "2" at 22.837,-52.12 h3
  text "3" at 93.337,-52.12 h3
  text "4" at 170.087,-52.12 h3

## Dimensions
50.86,-0.07 to 50.86,50.93 on M2_Dimensions
-0.14,50.93 to 50.86,50.93 on M2_Dimensions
